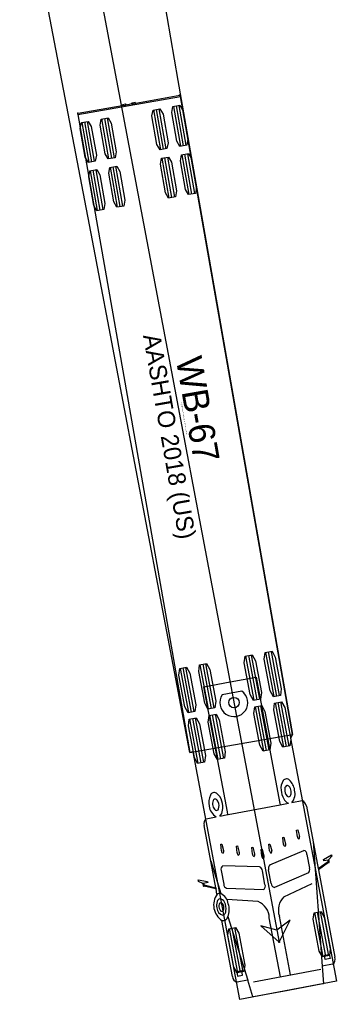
# Model space of a CAD drawing. Extents: x 973688 to 979179, y 703586 to 707602.
# Drawn here: x 978466.8 to 978492.6, y 703585.9 to 703665.8 of the extents above; entities that cross this region are included whole.
import ezdxf

# ---------------------------------------------------------------- set-up
doc = ezdxf.new("R2010")
doc.units = 0
doc.layers.add('T_Drafting', color=7, linetype='Continuous')

msp = doc.modelspace()

# ---------------------------------------------------------------- linework, layer by layer
at = {"layer": 'T_Drafting'}
for p, q in [((978473.306, 703668.114), (978487.907, 703590.57)), ((978471.498, 703658.108), (978479.87, 703659.577)), ((978475.149, 703658.82), (978475.411, 703658.866)), ((978475.672, 703658.912), (978475.684, 703658.842)), ((978475.934, 703658.958), (978476.195, 703659.004)), ((978478.261, 703655.224), (978477.691, 703658.475)), ((978478.486, 703655.264), (978477.916, 703658.514)), ((978478.712, 703655.303), (978478.142, 703658.554)), ((978479.886, 703655.509), (978479.316, 703658.76)), ((978480.112, 703655.549), (978479.542, 703658.799)), ((978480.337, 703655.589), (978479.767, 703658.839)), ((978474.042, 703654.484), (978473.472, 703657.735)), ((978474.268, 703654.524), (978473.697, 703657.774)), ((978474.493, 703654.563), (978473.923, 703657.814)), ((978472.417, 703654.199), (978471.846, 703657.45)), ((978472.642, 703654.239), (978472.072, 703657.489)), ((978472.868, 703654.278), (978472.298, 703657.529)), ((978478.952, 703651.284), (978478.382, 703654.535)), ((978479.178, 703651.324), (978478.607, 703654.574)), ((978479.403, 703651.364), (978478.833, 703654.614)), ((978480.577, 703651.57), (978480.007, 703654.82)), ((978480.803, 703651.609), (978480.233, 703654.86)), ((978481.028, 703651.649), (978480.458, 703654.899)), ((978473.333, 703650.299), (978472.763, 703653.549)), ((978473.559, 703650.339), (978472.989, 703653.589)), ((978474.733, 703650.544), (978474.163, 703653.795)), ((978474.959, 703650.584), (978474.388, 703653.834)), ((978475.184, 703650.624), (978474.614, 703653.874)), ((978473.108, 703650.259), (978472.538, 703653.51)), ((978485.883, 703610.303), (978485.205, 703613.906)), ((978486.108, 703610.345), (978485.43, 703613.949)), ((978486.334, 703610.388), (978485.655, 703613.991)), ((978487.505, 703610.608), (978486.826, 703614.212)), ((978487.73, 703610.651), (978487.051, 703614.254)), ((978487.955, 703610.693), (978487.277, 703614.297)), ((978480.544, 703609.298), (978479.865, 703612.901)), ((978480.769, 703609.34), (978480.09, 703612.943)), ((978480.994, 703609.382), (978480.316, 703612.986)), ((978482.165, 703609.603), (978481.487, 703613.206)), ((978482.39, 703609.645), (978481.712, 703613.249)), ((978482.616, 703609.688), (978481.937, 703613.291)), ((978484.866, 703611.06), (978483.278, 703610.761)), ((978486.66, 703606.176), (978485.982, 703609.779)), ((978486.886, 703606.218), (978486.207, 703609.821)), ((978487.111, 703606.26), (978486.432, 703609.864)), ((978488.282, 703606.481), (978487.603, 703610.084)), ((978488.507, 703606.523), (978487.829, 703610.127)), ((978488.732, 703606.566), (978488.054, 703610.169)), ((978481.546, 703605.213), (978480.868, 703608.816)), ((978481.771, 703605.255), (978481.093, 703608.858)), ((978482.942, 703605.476), (978482.264, 703609.079)), ((978483.168, 703605.518), (978482.489, 703609.121)), ((978483.393, 703605.56), (978482.714, 703609.164)), ((978481.321, 703605.17), (978480.642, 703608.774)), ((978483.744, 703600.98), (978487.999, 703601.781)), ((978489.335, 703599.719), (978489.424, 703599.736)), ((978489.398, 703599.172), (978489.335, 703599.719)), ((978489.424, 703599.736), (978489.564, 703599.203)), ((978483.161, 703598.557), (978483.249, 703598.573)), ((978483.224, 703598.009), (978483.161, 703598.557)), ((978483.249, 703598.573), (978483.39, 703598.04)), ((978484.429, 703598.403), (978484.517, 703598.419)), ((978484.492, 703597.855), (978484.429, 703598.403)), ((978484.517, 703598.419), (978484.657, 703597.887)), ((978487.076, 703598.561), (978487.164, 703598.578)), ((978487.139, 703598.014), (978487.076, 703598.561)), ((978487.164, 703598.578), (978487.304, 703598.045)), ((978488.21, 703599.115), (978488.298, 703599.131)), ((978488.279, 703598.543), (978488.21, 703599.115)), ((978488.298, 703599.131), (978488.444, 703598.574)), ((978490.685, 703598.787), (978491.42, 703588.613)), ((978485.687, 703598.3), (978485.775, 703598.316)), ((978485.75, 703597.752), (978485.687, 703598.3)), ((978485.775, 703598.316), (978485.916, 703597.783)), ((978486.438, 703598.127), (978486.527, 703598.144)), ((978486.502, 703597.58), (978486.438, 703598.127)), ((978486.527, 703598.144), (978486.667, 703597.611)), ((978487.152, 703596.875), (978489.918, 703598.052)), ((978490.181, 703597.724), (978490.39, 703596.613)), ((978482.331, 703597.214), (978483.161, 703594.533)), ((978486.318, 703596.718), (978483.313, 703596.808)), ((978491.897, 703597.259), (978491.925, 703597.263)), ((978491.925, 703597.263), (978491.944, 703597.284)), ((978483.187, 703596.407), (978483.396, 703595.296)), ((978486.758, 703595.273), (978486.549, 703596.384)), ((978487.267, 703595.369), (978487.058, 703596.48)), ((978490.296, 703596.219), (978487.53, 703595.042)), ((978491.101, 703596.576), (978491.119, 703596.478)), ((978481.73, 703595.344), (978481.705, 703595.356)), ((978481.757, 703595.35), (978481.73, 703595.344)), ((978488.297, 703594.279), (978490.605, 703595.357)), ((978482.748, 703595.003), (978482.766, 703594.905)), ((978483.627, 703594.963), (978486.632, 703594.873)), ((978486.195, 703593.883), (978483.64, 703594.049)), ((978491.502, 703589.381), (978490.823, 703592.985)), ((978491.727, 703589.424), (978491.048, 703593.027)), ((978491.952, 703589.466), (978491.274, 703593.07)), ((978483.743, 703592.654), (978485.347, 703587.469)), ((978488.015, 703587.743), (978487.11, 703592.55)), ((978488.835, 703587.897), (978487.93, 703592.704)), ((978484.541, 703588.071), (978483.862, 703591.674)), ((978484.766, 703588.113), (978484.087, 703591.716)), ((978484.991, 703588.156), (978484.313, 703591.759)), ((978491.598, 703589.497), (978492.003, 703589.573)), ((978491.663, 703589.147), (978491.598, 703589.497)), ((978492.069, 703589.223), (978491.663, 703589.147)), ((978492.003, 703589.573), (978492.069, 703589.223)), ((978484.86, 703588.228), (978484.454, 703588.152)), ((978484.454, 703588.152), (978484.52, 703587.802)), ((978484.926, 703587.878), (978484.86, 703588.228)), ((978485.834, 703587.332), (978491.301, 703588.361)), ((978484.52, 703587.802), (978484.926, 703587.878))]:
    msp.add_line(p, q, dxfattribs=at)
for points in [[(978477.849, 703671.335), (978479.646, 703660.883), (978489.003, 703607.513), (978488.843, 703607.215), (978492.578, 703587.379), (978484.716, 703585.899), (978480.915, 703606.086), (978480.631, 703606.044), (978472.708, 703647.818), (978466.758, 703678.927)], [(978471.508, 703658.182), (978471.487, 703658.178), (978471.499, 703658.108), (978472.477, 703652.526), (978480.631, 703606.044), (978484.817, 703606.779), (978489.003, 703607.513), (978480.85, 703653.995), (978479.87, 703659.577), (978479.858, 703659.646), (978479.836, 703659.642)], [(978479.812, 703659.638), (978479.812, 703659.638), (978476.231, 703659.01), (978476.195, 703659.004), (978476.183, 703659.073), (978476.182, 703659.073), (978475.919, 703659.027)], [(978475.401, 703658.936), (978475.138, 703658.89), (978475.137, 703658.889), (978475.149, 703658.82), (978475.114, 703658.814), (978471.533, 703658.186), (978471.532, 703658.186)], [(978475.927, 703658.957), (978475.414, 703658.867)], [(978483.069, 703600.852), (978483.743, 703600.979), (978483.7, 703601.214), (978481.782, 703611.396), (978483.91, 703611.797), (978486.038, 703612.198), (978487.955, 703602.015), (978488, 703601.781), (978488.674, 703601.908)], [(978488.951, 703601.96), (978489.782, 703602.116)], [(978490.143, 703601.663), (978491.101, 703596.576), (978491.906, 703597.14), (978491.906, 703597.14), (978491.912, 703597.178), (978491.912, 703597.179), (978491.911, 703597.18), (978491.897, 703597.259), (978491.896, 703597.259), (978491.551, 703597.21), (978491.532, 703597.312), (978492.192, 703597.697), (978492.193, 703597.697), (978492.215, 703597.581), (978492.213, 703597.578), (978491.945, 703597.285), (978491.944, 703597.283), (978491.959, 703597.198)], [(978481.962, 703600.644), (978482.792, 703600.8)], [(978481.722, 703595.27), (978481.705, 703595.355), (978481.703, 703595.357), (978481.347, 703595.532), (978481.344, 703595.534), (978481.322, 703595.65), (978481.324, 703595.651), (978482.079, 703595.532), (978482.098, 703595.43), (978481.758, 703595.35), (978481.758, 703595.349), (978481.773, 703595.271), (978481.773, 703595.27), (978481.773, 703595.269), (978481.792, 703595.236), (978481.792, 703595.236), (978482.748, 703595.003), (978481.79, 703600.09)], [(978491.941, 703597.058), (978491.128, 703596.484), (978491.121, 703596.47), (978492.464, 703589.339)], [(978482.846, 703594.478), (978482.768, 703594.897), (978482.756, 703594.907), (978481.79, 703595.147)], [(978484.11, 703587.766), (978483.251, 703592.33)], [(978487.907, 703590.57), (978488.81, 703592.355), (978487.722, 703591.553), (978486.417, 703591.904), (978487.907, 703590.57)], [(978492.27, 703588.773), (978491.428, 703588.615), (978491.42, 703588.611), (978491.523, 703587.181), (978491.461, 703587.169), (978488.647, 703586.639), (978485.833, 703586.109), (978485.771, 703586.098), (978485.348, 703587.468), (978485.338, 703587.468), (978484.496, 703587.309)]]:
    msp.add_lwpolyline(points, dxfattribs=at)
for points in [[(978478.768, 703655.313), (978478.205, 703655.214), (978477.955, 703655.64), (978477.545, 703657.98), (978477.635, 703658.465), (978478.198, 703658.564), (978478.448, 703658.138), (978478.858, 703655.798)], [(978480.393, 703655.598), (978479.83, 703655.5), (978479.58, 703655.925), (978479.17, 703658.265), (978479.26, 703658.75), (978479.823, 703658.849), (978480.073, 703658.423), (978480.483, 703656.083)], [(978474.549, 703654.573), (978473.986, 703654.474), (978473.736, 703654.9), (978473.326, 703657.24), (978473.416, 703657.725), (978473.979, 703657.824), (978474.229, 703657.398), (978474.639, 703655.058)], [(978472.924, 703654.288), (978472.361, 703654.189), (978472.111, 703654.615), (978471.701, 703656.955), (978471.791, 703657.44), (978472.354, 703657.539), (978472.603, 703657.113), (978473.014, 703654.773)], [(978479.459, 703651.373), (978478.896, 703651.275), (978478.646, 703651.7), (978478.236, 703654.04), (978478.326, 703654.525), (978478.889, 703654.624), (978479.139, 703654.199), (978479.549, 703651.858)], [(978481.084, 703651.659), (978480.521, 703651.56), (978480.271, 703651.985), (978479.861, 703654.325), (978479.951, 703654.81), (978480.514, 703654.909), (978480.764, 703654.484), (978481.174, 703652.143)], [(978473.615, 703650.348), (978473.052, 703650.25), (978472.802, 703650.675), (978472.392, 703653.015), (978472.482, 703653.5), (978473.045, 703653.599), (978473.295, 703653.173), (978473.705, 703650.833)], [(978475.24, 703650.633), (978474.677, 703650.535), (978474.427, 703650.96), (978474.017, 703653.3), (978474.107, 703653.785), (978474.67, 703653.884), (978474.92, 703653.459), (978475.33, 703651.118)], [(978486.389, 703610.398), (978485.827, 703610.293), (978485.563, 703610.765), (978485.074, 703613.36), (978485.149, 703613.896), (978485.711, 703614.002), (978485.975, 703613.529), (978486.464, 703610.935)], [(978488.011, 703610.704), (978487.449, 703610.598), (978487.184, 703611.07), (978486.696, 703613.665), (978486.77, 703614.201), (978487.332, 703614.307), (978487.597, 703613.835), (978488.085, 703611.24)], [(978481.05, 703609.393), (978480.488, 703609.287), (978480.223, 703609.76), (978479.735, 703612.354), (978479.809, 703612.89), (978480.371, 703612.996), (978480.636, 703612.524), (978481.124, 703609.929)], [(978482.671, 703609.698), (978482.109, 703609.592), (978481.845, 703610.065), (978481.356, 703612.659), (978481.431, 703613.196), (978481.993, 703613.302), (978482.257, 703612.829), (978482.746, 703610.235)], [(978487.167, 703606.271), (978486.604, 703606.165), (978486.34, 703606.638), (978485.852, 703609.232), (978485.926, 703609.768), (978486.488, 703609.874), (978486.752, 703609.402), (978487.241, 703606.807)], [(978488.788, 703606.576), (978488.226, 703606.47), (978487.962, 703606.943), (978487.473, 703609.537), (978487.547, 703610.074), (978488.11, 703610.18), (978488.374, 703609.707), (978488.862, 703607.113)], [(978481.827, 703605.266), (978481.265, 703605.16), (978481.001, 703605.632), (978480.512, 703608.227), (978480.586, 703608.763), (978481.149, 703608.869), (978481.413, 703608.396), (978481.901, 703605.802)], [(978483.449, 703605.571), (978482.886, 703605.465), (978482.622, 703605.938), (978482.134, 703608.532), (978482.208, 703609.068), (978482.77, 703609.174), (978483.034, 703608.702), (978483.523, 703606.107)], [(978492.008, 703589.477), (978491.446, 703589.371), (978491.181, 703589.844), (978490.693, 703592.438), (978490.767, 703592.974), (978491.329, 703593.08), (978491.594, 703592.608), (978492.082, 703590.013)], [(978487.907, 703590.57), (978488.81, 703592.355), (978487.722, 703591.553), (978486.417, 703591.904)], [(978485.047, 703588.166), (978484.485, 703588.06), (978484.22, 703588.533), (978483.732, 703591.127), (978483.806, 703591.664), (978484.368, 703591.769), (978484.633, 703591.297), (978485.121, 703588.702)]]:
    msp.add_lwpolyline(points, close=True, dxfattribs=at)
for centre, radius in [((978479.819, 703659.674), 0.0266), ((978471.514, 703658.217), 0.0266), ((978484.232, 703610.116), 0.424), ((978487.907, 703590.57), 0.0417)]:
    msp.add_circle(centre, radius, dxfattribs=at)
for centre, radius, start, end in [((978479.819, 703659.674), 0.0363, 299.02658, 260.18793), ((978475.407, 703658.901), 0.0354, 104.24067, 276.42613), ((978475.407, 703658.901), 0.0352, 280.92345, 99.92386), ((978475.925, 703658.992), 0.0352, 99.9744, 278.97481), ((978475.926, 703658.992), 0.0353, 283.28531, 101.63496), ((978471.159, 703660.173), 2.022, 279.94913, 280.63289), ((978484.222, 703610.116), 1.143, 145.66385, 55.66385), ((978489.192, 703603.131), 1.136, 146.42782, 187.94856), ((978488.515, 703603.542), 0.346, 44.05655, 141.06961), ((978488.728, 703603.06), 0.362, 134.96041, 184.0014), ((978488.578, 703603.181), 0.172, 40.96546, 128.11605), ((978488.229, 703602.834), 0.664, 5.56768, 43.7894), ((978487.774, 703602.77), 1.416, 8.592, 45.65986), ((978483.594, 703601.983), 1.416, 155.66785, 192.7357), ((978482.623, 703602.433), 0.346, 60.2581, 157.27115), ((978482.142, 703601.804), 1.136, 13.37914, 54.89989), ((978489.792, 703603.11), 1.73, 184.49049, 209.289), ((978489.097, 703602.982), 0.732, 175.83768, 222.07211), ((978488.684, 703602.598), 0.169, 219.09818, 319.2169), ((978488.381, 703602.782), 0.522, 325.66922, 12.83334), ((978488.077, 703602.686), 1.136, 320.29379, 15.08508), ((978483.342, 703601.794), 1.136, 186.24262, 241.03392), ((978483.147, 703601.877), 0.664, 157.53831, 195.76002), ((978483.024, 703601.774), 0.522, 188.49437, 235.65849), ((978482.695, 703602.073), 0.172, 73.21166, 160.36225), ((978482.6, 703601.906), 0.362, 17.32631, 66.36729), ((978482.285, 703601.699), 0.732, 339.25559, 25.49003), ((978481.591, 703601.565), 1.73, 352.03871, 16.83721), ((978488.935, 703602.588), 0.729, 206.47234, 248.98634), ((978489.535, 703601.548), 0.619, 10.66183, 66.50354), ((978482.809, 703601.491), 0.169, 242.11081, 342.22953), ((978482.578, 703601.391), 0.729, 312.34137, 354.85537), ((978482.398, 703600.205), 0.619, 134.82417, 190.66588), ((978489.43, 703599.121), 0.157, 304.20984, 31.3195), ((978488.457, 703598.56), 0.184, 177.61703, 249.50905), ((978488.305, 703598.517), 0.157, 304.20984, 31.3195), ((978489.582, 703599.164), 0.184, 177.61703, 249.50905), ((978483.379, 703597.982), 0.157, 170.00821, 257.11787), ((978483.221, 703597.966), 0.184, 311.81866, 23.71067), ((978484.646, 703597.828), 0.157, 170.00821, 257.11787), ((978484.489, 703597.813), 0.184, 311.81866, 23.71067), ((978485.905, 703597.725), 0.157, 170.00821, 257.11787), ((978485.747, 703597.709), 0.184, 311.81866, 23.71067), ((978486.533, 703597.529), 0.157, 304.20984, 31.3195), ((978487.323, 703598.006), 0.184, 177.61703, 249.50905), ((978487.17, 703597.963), 0.157, 304.20984, 31.3195), ((978489.849, 703597.727), 0.332, 359.58526, 78.00726), ((978483.495, 703596.53), 0.332, 123.32045, 201.74245), ((978486.656, 703597.553), 0.157, 170.00821, 257.11787), ((978487.425, 703596.601), 0.387, 134.99915, 198.22622), ((978491.943, 703597.11), 0.0522, 266.92664, 11.78126), ((978491.887, 703597.118), 0.108, 1.50503, 47.68752), ((978486.162, 703596.363), 0.387, 3.10149, 66.32855), ((978490.023, 703596.492), 0.387, 314.9967, 18.22867), ((978481.818, 703595.222), 0.108, 153.64018, 199.82268), ((978483.782, 703595.317), 0.387, 183.09904, 246.331), ((978486.496, 703595.136), 0.296, 297.38261, 27.68029), ((978487.561, 703595.336), 0.296, 173.64742, 263.9451), ((978481.769, 703595.194), 0.0522, 189.54645, 294.40107), ((978484.103, 703593.601), 1.53, 145.15659, 236.16564), ((978483.06, 703594.201), 0.347, 72.99106, 127.80165), ((978482.648, 703593.519), 1.136, 9.3684, 63.17096), ((978483.844, 703593.582), 1.03, 163.48751, 191.87402), ((978483.166, 703593.81), 0.317, 106.51405, 168.10645), ((978483.594, 703593.509), 0.589, 163.41938, 206.40209), ((978483.191, 703593.625), 0.17, 108.33292, 162.39725), ((978483.048, 703593.674), 0.44, 22.4581, 86.27094), ((978483.108, 703593.526), 0.263, 9.59877, 83.50069), ((978482.401, 703593.29), 1.189, 351.79506, 27.68437), ((978482.136, 703593.22), 1.704, 340.58454, 16.4926), ((978485.594, 703592.49), 1.517, 2.2439, 66.67131), ((978489.363, 703593.2), 1.517, 134.65639, 199.08381), ((978483.47, 703593.384), 0.634, 181.24772, 257.24943), ((978483.278, 703593.315), 0.223, 197.89875, 267.50125), ((978483.226, 703593.244), 0.158, 285.63507, 347.14783), ((978483.212, 703593.112), 0.366, 288.71619, 1.19718), ((978482.827, 703593.37), 0.575, 343.73897, 20.3093), ((978483.331, 703592.762), 0.425, 258.72679, 345.26315), ((978492.005, 703589.18), 0.486, 303.12682, 19.07792), ((978484.596, 703587.785), 0.486, 182.24978, 258.20089)]:
    msp.add_arc(centre, radius, start, end, dxfattribs=at)
for centre, major_axis, start_param, end_param in [((978491.951, 703597.127), (-0.0145, 0.0769), 1.301202, 2.571945), ((978491.951, 703597.127), (0.0145, -0.0769), 2.615166, 3.884468), ((978481.756, 703595.208), (0.0145, -0.0769), 2.398717, 3.668019), ((978481.756, 703595.208), (0.0145, -0.0769), 0.569648, 1.840391)]:
    msp.add_ellipse(centre, major_axis=major_axis, ratio=0.544872, start_param=start_param, end_param=end_param, dxfattribs=at)

# ---------------------------------------------------------------- texts
for s, height, p in [('AASHTO 2018 (US)', 1.41667, (978476.814, 703640.062)), ('WB-67', 2.125, (978479.488, 703638.142)), ('(c) 2021 Transoft Solutions, Inc. All rights reserved.', 0.085, (978479.897, 703634.579))]:
    msp.add_text(s, height=height, rotation=279.94913, dxfattribs=at).set_placement(p)

doc.saveas('drawing.dxf')
